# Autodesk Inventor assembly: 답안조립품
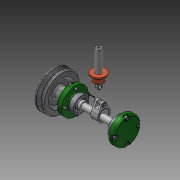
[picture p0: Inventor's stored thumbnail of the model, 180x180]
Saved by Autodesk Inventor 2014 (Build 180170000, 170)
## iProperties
Created: 2016-02
Part Number: 답안조립품
Document SubType Name: Assembly
Designer: G.C.Oh
Author: G.C.Oh
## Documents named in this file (16)
- C:\Users\Administrator\Desktop\460211V1034\답안조립품.iam
- C:\Users\Administrator\Desktop\460211V1034\1-본체.ipt
- C:\Users\Administrator\Desktop\460211V1034\V벨트풀리.ipt
- C:\Users\Administrator\Desktop\460211V1034\고정핀 1.2 x 10.ipt
- C:\Users\Administrator\Desktop\460211V1034\뒤커버.ipt
- C:\Users\Administrator\Desktop\460211V1034\링크.ipt
- C:\Users\Administrator\Desktop\460211V1034\멈춤나사 M3x8.ipt
- C:\Users\Administrator\Desktop\460211V1034\베어링 12 x 32 x 10.ipt
- C:\Users\Administrator\Desktop\460211V1034\볼트 M4 x 12.ipt
- C:\Users\Administrator\Desktop\460211V1034\부시.ipt
- C:\Users\Administrator\Desktop\460211V1034\슬라이드.ipt
- C:\Users\Administrator\Desktop\460211V1034\앞커버.ipt
- C:\Users\Administrator\Desktop\460211V1034\오일실 12 25 7.ipt
- C:\Users\Administrator\Desktop\460211V1034\키 4 x 4 x 10.ipt
- C:\Users\Administrator\Desktop\460211V1034\편심축.ipt
- C:\Users\Administrator\Desktop\460211V1034\핀 5 x 18.ipt
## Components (12 placed, 5 different names)
1. 1-본체:1 — 각도:1, 각도:2
2. V벨트풀리:1 — 각도:4
3. 고정핀 1.2 x 10:1
4. 핀 5 x 18:1
5. ISO 4762 M4 x 12:2 — 각도:1
6. ISO 4762 M4 x 12:3
7. ISO 4762 M4 x 12:4
8. ISO 4762 M4 x 12:5
9. ISO 4762 M4 x 12:1 — 각도:2
10. ISO 4762 M4 x 12:6
11. ISO 4762 M4 x 12:7
12. ISO 4762 M4 x 12:8
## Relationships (3: Angle 3)
- 각도:1 [Angle]: 1-본체:1 ↔ ISO 4762 M4 x 12:2
- 각도:2 [Angle]: 1-본체:1 ↔ ISO 4762 M4 x 12:1
- 각도:4 [Angle]: V벨트풀리:1
